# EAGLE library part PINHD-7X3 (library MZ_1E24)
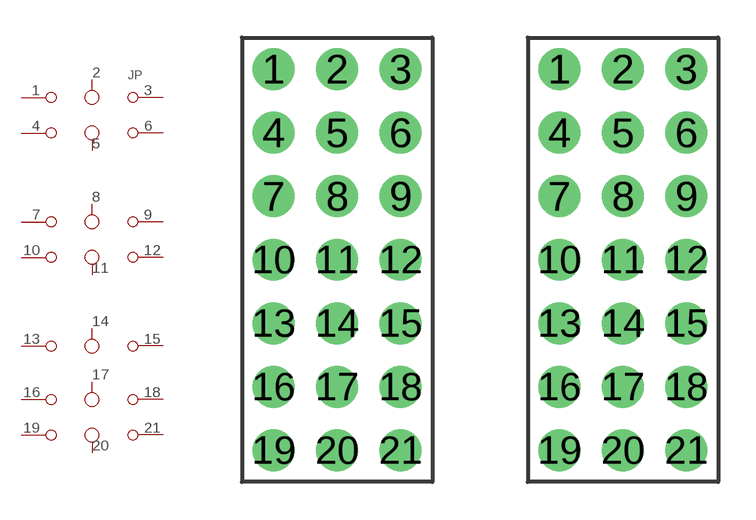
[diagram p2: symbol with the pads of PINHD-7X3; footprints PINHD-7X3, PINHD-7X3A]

Designator prefix JP

## PINHD-7X3  [PINHD-7X3]
1  1  pas
2  2  pas
3  3  pas
4  4  pas
5  5  pas
6  6  pas
7  7  pas
8  8  pas
9  9  pas
10  10  pas
11  11  pas
12  12  pas
13  13  pas
14  14  pas
15  15  pas
16  16  pas
17  17  pas
18  18  pas
19  19  pas
20  20  pas
21  21  pas

## PINHD-7X3A  [PINHD-7X3A]
Pads as for PINHD-7X3

## PINHD-7X3B  [PINHD-7X3B]
Pads as for PINHD-7X3

## Footprint PINHD-7X3 (pad centres in mm)
drill 1.016 pad 1.676 round: 1 -2.54,7.62; 2 0,7.62; 3 2.54,7.62; 4 -2.54,5.08; 5 0,5.08; 6 2.54,5.08; 7 -2.54,2.54; 8 0,2.54; 9 2.54,2.54; 10 -2.54,0; 11 0,0; 12 2.54,0; 13 -2.54,-2.54; 14 0,-2.54; 15 2.54,-2.54; 16 -2.54,-5.08; 17 0,-5.08; 18 2.54,-5.08; 19 -2.54,-7.62; 20 0,-7.62; 21 2.54,-7.62

## Footprint PINHD-7X3A (pad centres in mm)
drill 1.016 pad 1.676 round: 1 -2.54,7.62; 2 0,7.62; 3 2.54,7.62; 4 -2.54,5.08; 5 0,5.08; 6 2.54,5.08; 7 -2.54,2.54; 8 0,2.54; 9 2.54,2.54; 10 -2.54,0; 11 0,0; 12 2.54,0; 13 -2.54,-2.54; 14 0,-2.54; 15 2.54,-2.54; 16 -2.54,-5.08; 17 0,-5.08; 18 2.54,-5.08; 19 -2.54,-7.62; 20 0,-7.62; 21 2.54,-7.62

## Footprint PINHD-7X3B (pad centres in mm)
drill 1.016 pad 1.676 round: 1 -2.54,7.62; 2 0,7.62; 3 2.54,7.62; 4 -2.54,5.08; 5 0,5.08; 6 2.54,5.08; 7 -2.54,2.54; 8 0,2.54; 9 2.54,2.54; 10 -2.54,0; 11 0,0; 12 2.54,0; 13 -2.54,-2.54; 14 0,-2.54; 15 2.54,-2.54; 16 -2.54,-5.08; 17 0,-5.08; 18 2.54,-5.08; 19 -2.54,-7.62; 20 0,-7.62; 21 2.54,-7.62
